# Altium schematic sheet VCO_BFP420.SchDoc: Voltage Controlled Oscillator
size A4; Author: Alemla; Revision: 1.2; SheetNumber: 3; SheetTotal: 7; SPICEModelCacheUMHTQHEF: <root> / <DocumentId>UMHTQHEF</DocumentId> / </root>
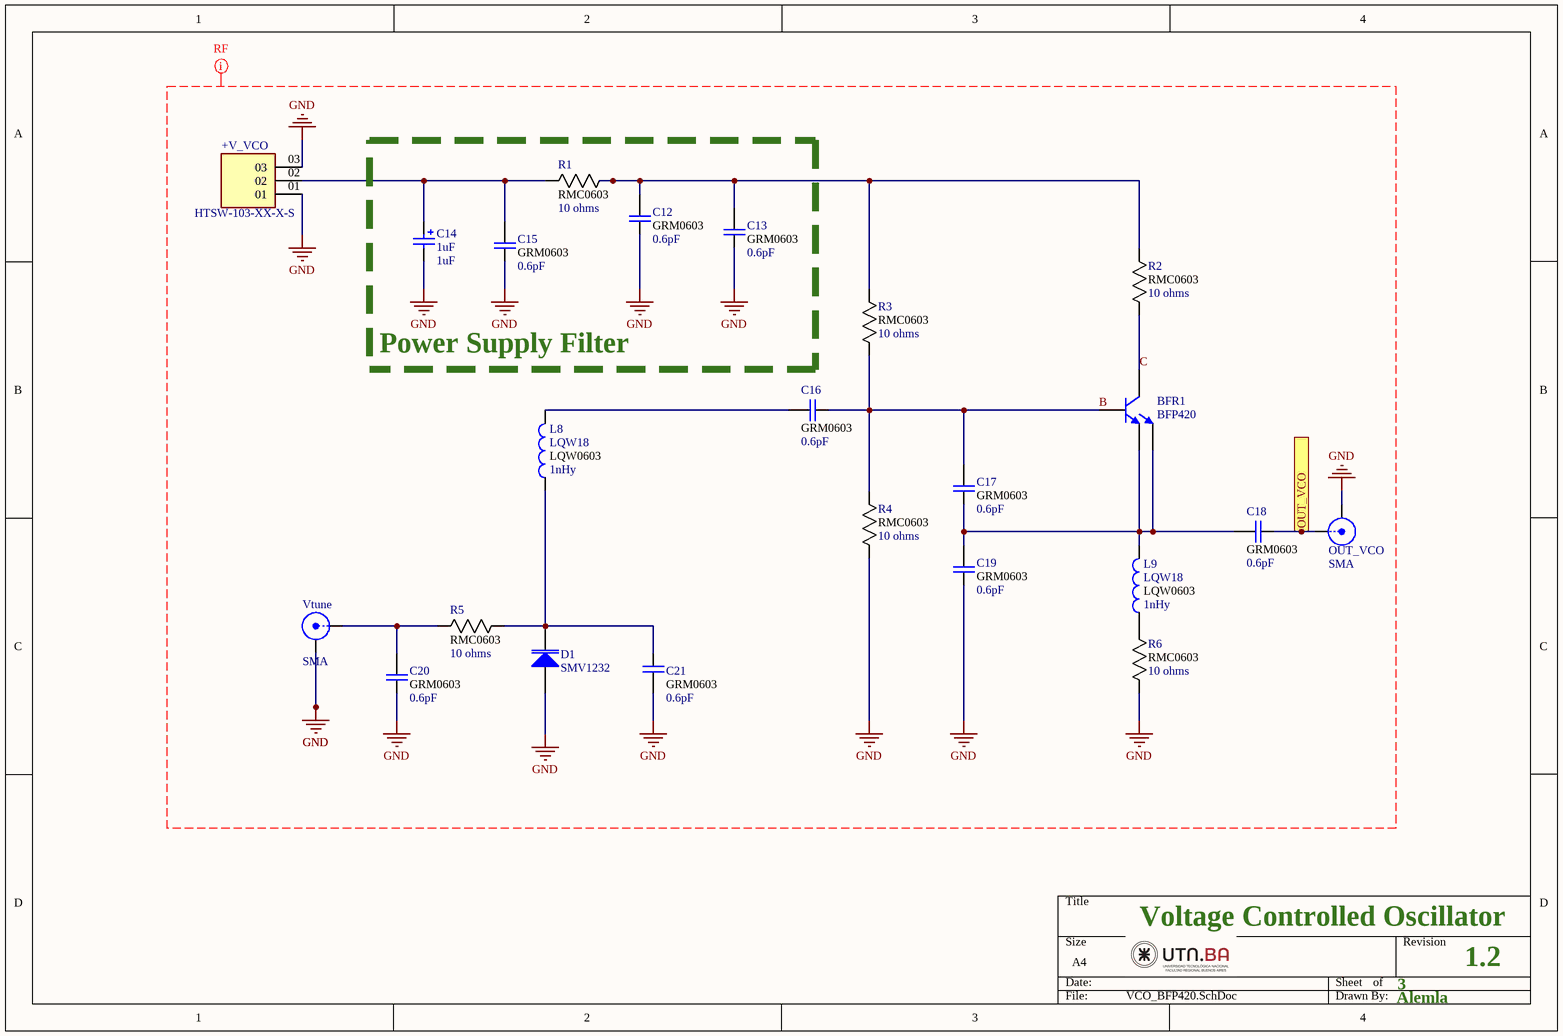
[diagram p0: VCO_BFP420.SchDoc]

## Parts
+V_VCO  HTSW-103-XX-X-S  [SAMTEC_HTSW-103-XX-X-S]
BFR1  BFP420  [SOT-343_N]
C12  value 0.6pF  footprint: GRM0603  [CAPC1608X90N]  (hidden comment: Cap 0603)
C13  value 0.6pF  footprint: GRM0603  [CAPC1608X90N]  (hidden comment: Cap 0603)
C14  1uF  [6-0805_N]
C15  value 0.6pF  footprint: GRM0603  [CAPC1608X90N]  (hidden comment: Cap 0603)
C16  value 0.6pF  footprint: GRM0603  [CAPC1608X90N]  (hidden comment: Cap 0603)
C17  value 0.6pF  footprint: GRM0603  [CAPC1608X90N]  (hidden comment: Cap 0603)
C18  value 0.6pF  footprint: GRM0603  [CAPC1608X90N]  (hidden comment: Cap 0603)
C19  value 0.6pF  footprint: GRM0603  [CAPC1608X90N]  (hidden comment: Cap 0603)
C20  value 0.6pF  footprint: GRM0603  [CAPC1608X90N]  (hidden comment: Cap 0603)
C21  value 0.6pF  footprint: GRM0603  [CAPC1608X90N]  (hidden comment: Cap 0603)
D1  SMV1232  [6-0805_N]
L8  LQW18  value 1nHy  Parameter 1: LQW0603  [INDC1608X100N]
L9  LQW18  value 1nHy  Parameter 1: LQW0603  [INDC1608X100N]
OUT_VCO  SMA  [SMA-142-0701-851]
R1  value 10 ohms  footprint: RMC0603  [RESC1508X55N]  (hidden comment: Resistor)
R2  value 10 ohms  footprint: RMC0603  [RESC1508X55N]  (hidden comment: Resistor)
R3  value 10 ohms  footprint: RMC0603  [RESC1508X55N]  (hidden comment: Resistor)
R4  value 10 ohms  footprint: RMC0603  [RESC1508X55N]  (hidden comment: Resistor)
R5  value 10 ohms  footprint: RMC0603  [RESC1508X55N]  (hidden comment: Resistor)
R6  value 10 ohms  footprint: RMC0603  [RESC1508X55N]  (hidden comment: Resistor)
Vtune  SMA  [SMA-142-0701-851]

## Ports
OUT_VCO (out)

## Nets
GND: +V_VCO.01 +V_VCO.03 C12.1 C13.1 C14.2 C15.1 C19.1 C20.1 C21.2 D1.1(A) OUT_VCO.2(Y) R4.1 R6.1 Vtune.2(Y)
B: BFR1.4(B) C16.1 C17.2 R3.1 R4.2
C: BFR1.2(C) R2.1
OUT_VCO: C18.1 OUT_VCO.1(X) ; port OUT_VCO
Net+V_VCO_02: +V_VCO.02 C14.1 C15.2 R1.1
NetBFR1_1: BFR1.1(E) BFR1.3(E) C17.1 C18.2 C19.2 L9.2
NetC12_2: C12.2 C13.2 R1.2 R2.2 R3.2
NetC16_2: C16.2 L8.2
NetC20_2: C20.2 R5.2 Vtune.1(X)
NetC21_1: C21.1 D1.2(K) L8.1 R5.1
NetL9_1: L9.1 R6.2

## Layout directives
net class RF50R: B, C, GND

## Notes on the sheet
- Power Supply Filter

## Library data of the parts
+V_VCO = HTSW-103-XX-X-S: Conn Unshrouded Header HDR 3 POS 2.54mm Solder ST Top Entry Thru-Hole Bag; MP: HTSW-103-08-S-S; MF: Samtec
BFR1 = BFR460: NPN Bipolar Transistor
C12 C13 C15-C21 = Cap: Capacitor GRM18 0603
C14 = Cap Pol2_1: Polarized Capacitor (Axial)
D1 = D Varactor: Variable Capacitance Diode; Note: Pin 2 is not connected and not drawn.
L8 L9 = LQW18: Ind RF Chip Wirewound 18nH 5% 100MHz 40Q-Factor 550mA 0603 Paper T/R; MP: LQW18AN18NJ00D
OUT_VCO Vtune = SMA: SMA Straight Connector
R1-R6 = Resistor: Resistor RMC0603; Mfr_Name: Stackpole International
